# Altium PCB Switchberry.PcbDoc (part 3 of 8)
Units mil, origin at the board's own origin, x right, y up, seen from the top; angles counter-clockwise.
Board outline 4500 x 3824.8 mil, 6 copper layers (L01-TOP, L02-GND, L03-SIG, L04-SIG, L05-GND, L06-BOT), stack 49.214 mil thick; 431 components, 322 nets, 1699 pads, 1274 vias.
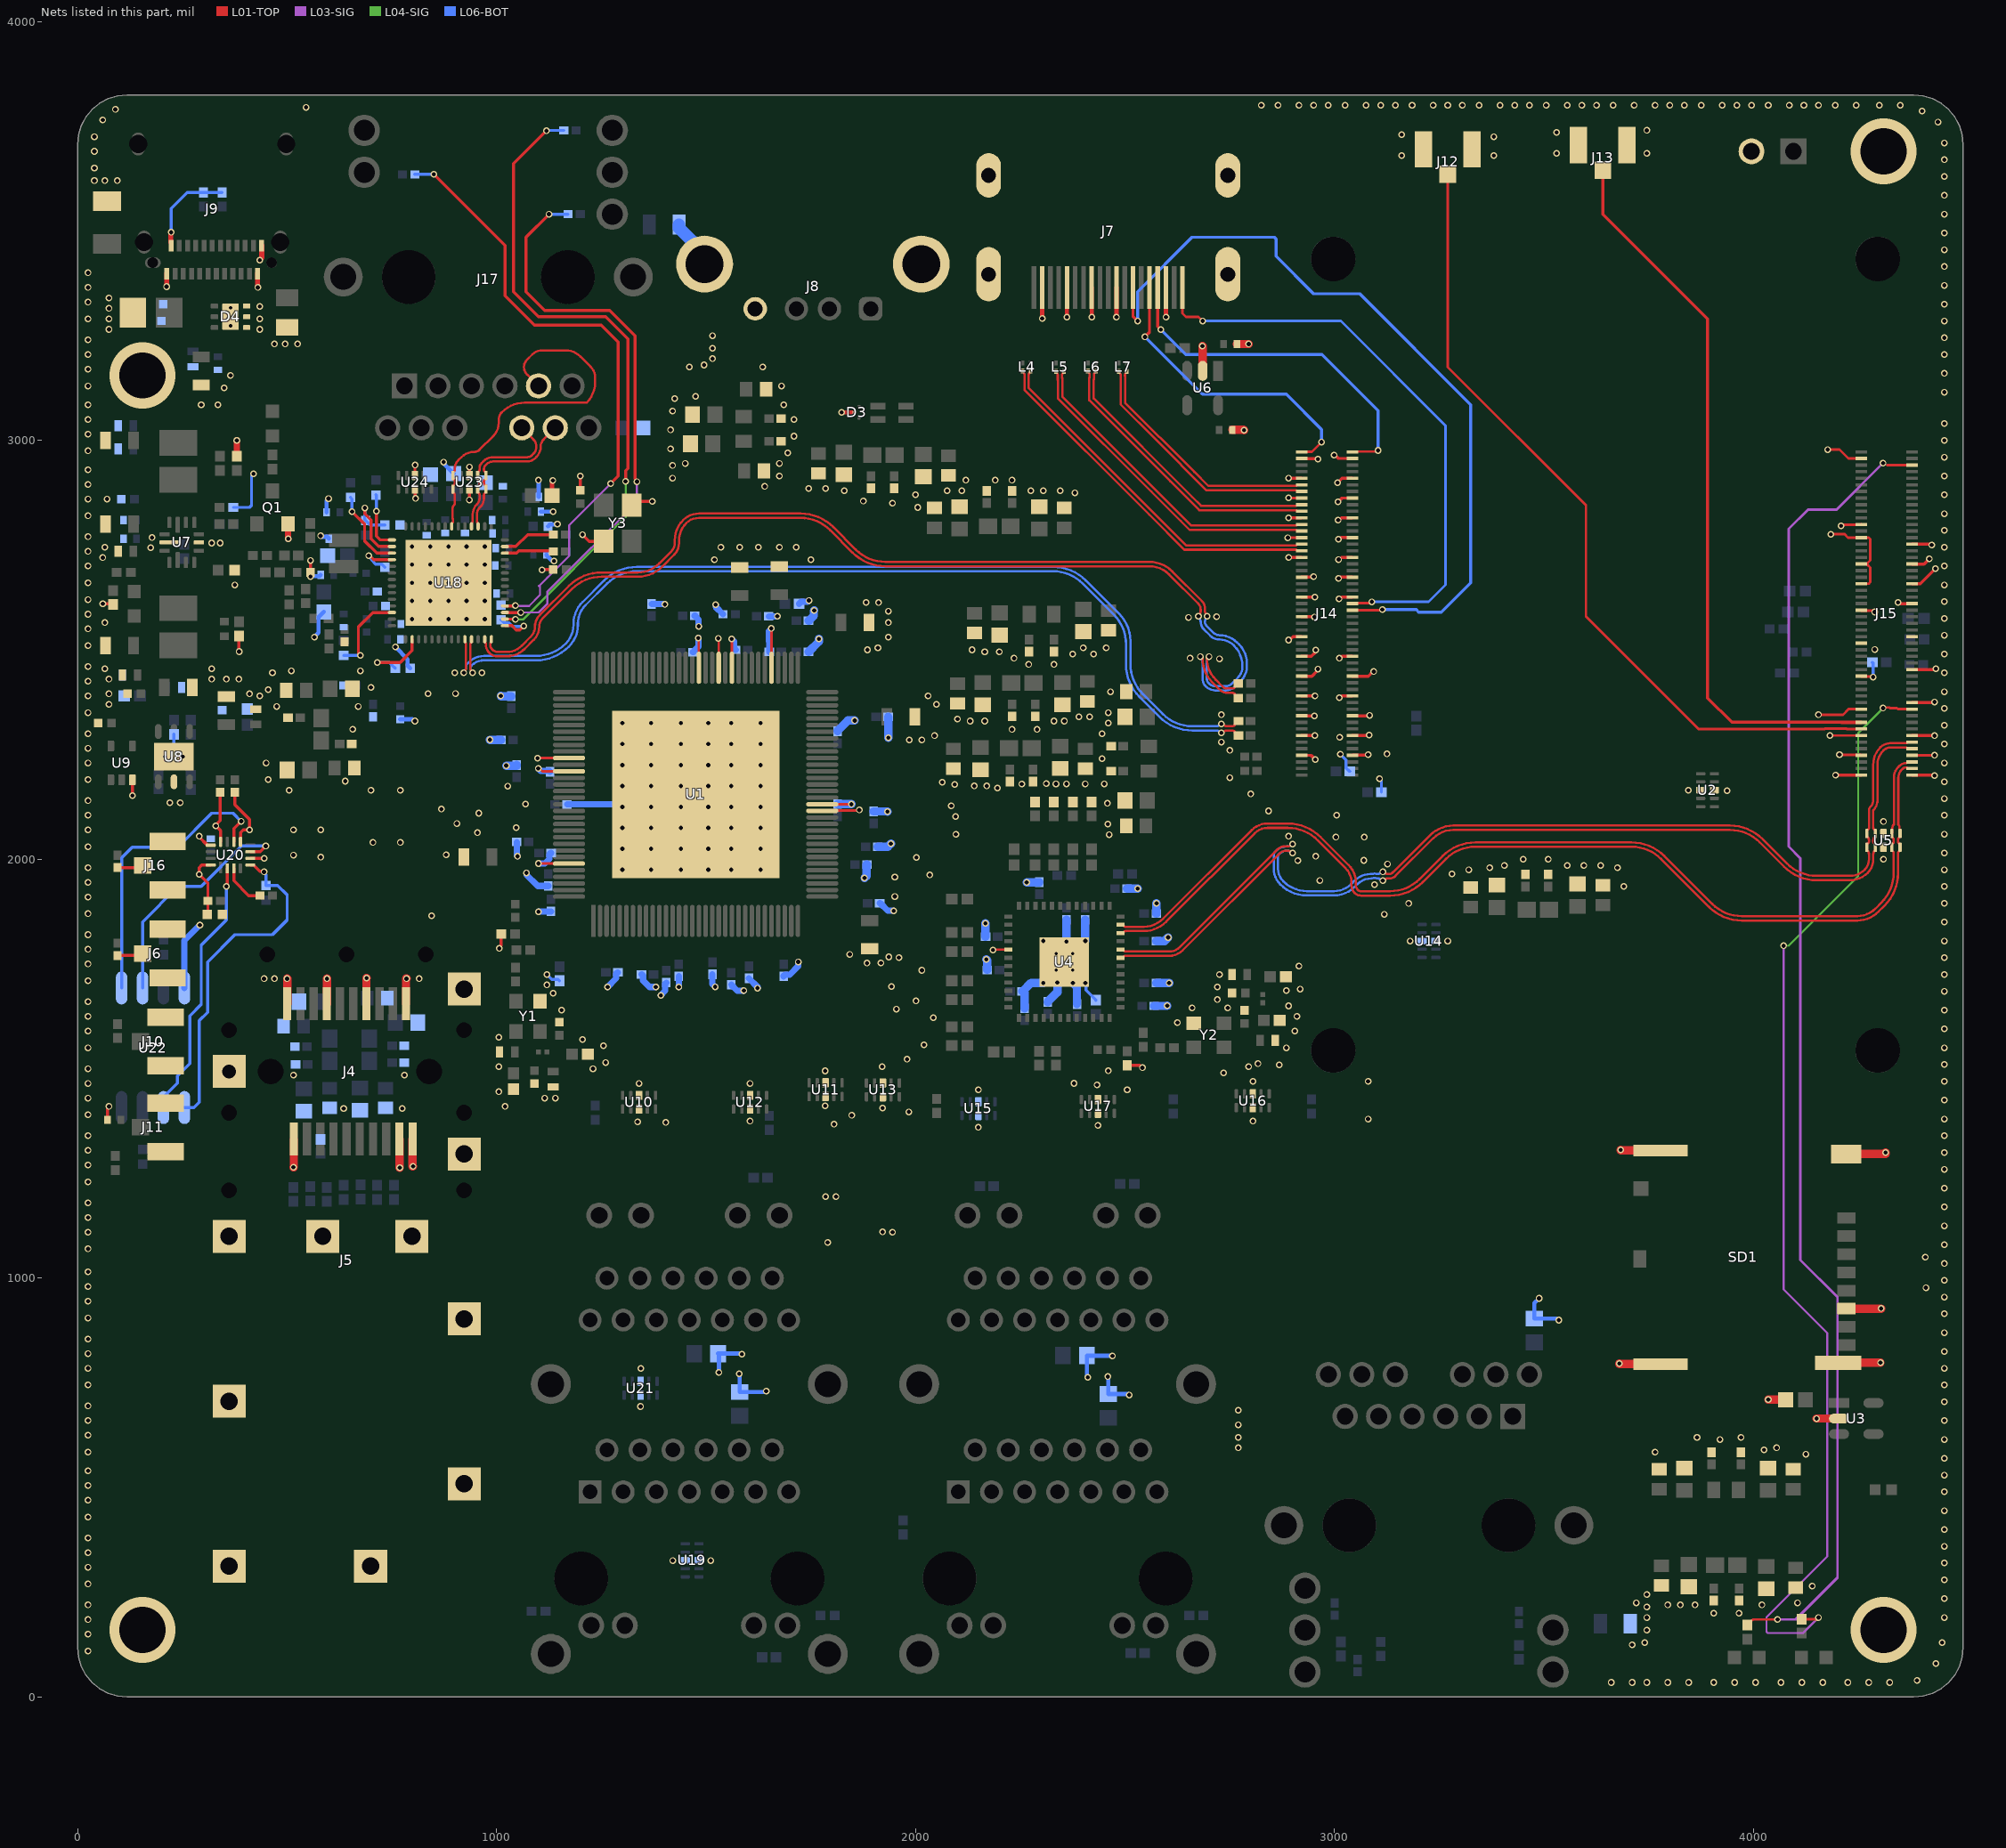
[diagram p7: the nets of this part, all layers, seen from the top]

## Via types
v1: diameter 16, hole 10, L01-TOP to L06-BOT, tented both sides, 1262 vias
v2: diameter 11.81, hole 7.87, L01-TOP to L06-BOT, tented both sides, 4 vias
v3: diameter 19.68, hole 7.87, L01-TOP to L06-BOT, tented both sides, 4 vias
v4: diameter 157.48, hole 110.24, L01-TOP to L06-BOT, tented both sides, 4 vias

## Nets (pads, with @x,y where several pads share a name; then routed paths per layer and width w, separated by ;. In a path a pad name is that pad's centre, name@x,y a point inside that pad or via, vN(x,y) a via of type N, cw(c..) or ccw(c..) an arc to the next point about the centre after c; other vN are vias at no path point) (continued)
ETH_PAIR2_N: J15.9 U4.8 U5.2 U5.9 | length 2538
  L01-TOP w5.38: U4.8@2488.86,1784.53 2490.49,1784.53 cw(c2490.49,1776.58) 2496.11,1782.2 ccw(c2501.72,1787.82) 2501.72,1779.87 2605.55,1779.87 ccw(c2605.55,1814.45) 2630,1790 2863.22,2023.22 cw(c2881.25,2005.19) 2881.25,2030.69 2888.06,2030.69 ccw(c2888.06,2039.76) 2894.47,2033.34 2895.09,2033.97 cw(c2900,2029.06) v1(2900,2036) ; v1(3115,1949) ccw(c3115,1955.94) 3119.91,1951.03 3120.53,1951.66 cw(c3126.94,1945.24) 3126.94,1954.31 3131.25,1954.31 ccw(c3131.25,1973.78) 3145.01,1960.01 3235,2050 cw(c3283.28,2001.72) 3283.28,2070 3943.56,2070 cw(c3943.56,1970) 4014.27,2040.71 4072.73,1982.26 ccw(c4150.78,2060.31) 4150.78,1949.93 4229.52,1949.93 ccw(c4229.52,2010.48) 4272.34,1967.66 ccw(c4240.17,1999.83) 4285.66,1999.83 4285.66,2012.52 cw(c4296.42,2012.52) 4288.81,2020.13 4289.07,2020.13 4289.69,2020.75 ccw(c4288.18,2022.26) 4290.31,2022.26 U5.2@4290.31,2028.56 4290.31,2033.98 ccw(c4286.05,2033.98) 4289.07,2037 4288.81,2037 4287.24,2038.57 cw(c4291.04,2042.37) 4285.66,2042.37 4285.66,2045.4 cw(c4296.42,2045.4) 4288.81,2053 4289.07,2053 4289.69,2053.63 ccw(c4288.18,2055.13) 4290.31,2055.13 U5.9@4290.31,2061.44 4290.31,2066.86 ccw(c4286.05,2066.86) 4289.07,2069.87 4288.81,2069.87 4287.24,2071.45 cw(c4291.04,2075.25) 4285.66,2075.25 4285.66,2116.42 cw(c4288.1,2116.42) 4286.38,2118.15 ccw(c4263.83,2140.69) 4295.72,2140.69 4295.72,2225.52 cw(c4344.49,2225.52) 4310,2260 cw(c4325.93,2244.07) 4325.93,2266.6 4363.47,2266.6 cw(c4363.47,2262.01) 4366.71,2265.26 ccw(c4369.95,2268.5) 4369.95,2263.91 J15.9@4377.9,2263.91
  L06-BOT w5.38: v1(2900,2036) ccw(c2900,2029.06) 2895.09,2033.97 cw(c2887.18,2041.88) 2887.18,2030.69 2885.73,2030.69 ccw(c2885.73,1994.38) 2860.05,2020.05 2859.29,2019.29 ccw(c2870.26,2008.33) 2854.75,2008.33 2854.75,1977.75 ccw(c2908.27,1977.75) 2870.43,1939.9 ccw(c2933.97,2003.45) 2933.97,1913.58 2998.42,1913.58 ccw(c2998.42,1983.07) 3047.56,1933.93 3054.2,1940.57 cw(c3087.38,1907.39) 3087.38,1954.31 3087.57,1954.37 cw(c3089.11,1949.22) 3088.34,1954.54 3093.05,1955.18 cw(c3095.11,1939.62) 3097.82,1955.08 3100.68,1954.57 ; 3100.7,1954.57 3101.27,1954.47 ccw(c3103.06,1964.69) 3103.06,1954.31 cw(c3103.06,1945.24) 3109.47,1951.66 3110.09,1951.03 ccw(c3115,1955.94) v1(3115,1949)
ETH_PAIR2_P: J15.11 U4.7 U5.1 U5.10 | length 2505.2
  L01-TOP w5.38: U4.7@2488.86,1764.84 2490.49,1764.84 ccw(c2490.49,1772.79) 2496.11,1767.17 cw(c2501.72,1761.55) 2501.72,1769.5 2605.55,1769.5 ccw(c2605.55,1814.45) 2637.34,1782.66 2869.04,2014.36 cw(c2883.4,2000) 2883.4,2020.31 2888.06,2020.31 cw(c2888.06,2011.24) 2894.47,2017.66 2895.09,2017.03 ccw(c2900,2021.94) v1(2900,2015) ; v1(3115,1970) cw(c3115,1963.06) 3119.91,1967.97 3120.53,1967.34 ccw(c3126.94,1973.76) 3126.94,1964.69 3129.1,1964.69 ccw(c3129.1,1978.97) 3139.19,1968.87 3227.66,2057.34 cw(c3283.28,2001.72) 3283.28,2080.38 3943.56,2080.38 cw(c3943.56,1970) 4021.61,2048.05 4080.07,1989.59 ccw(c4150.78,2060.31) 4150.78,1960.31 4229.52,1960.31 ccw(c4229.52,2010.48) 4265,1975 ccw(c4240.17,1999.83) 4275.28,1999.83 4275.28,2012.52 ccw(c4264.53,2012.52) 4272.13,2020.13 4271.88,2020.13 4271.25,2020.75 cw(c4272.76,2022.26) 4270.63,2022.26 U5.1@4270.63,2028.56 4270.63,2033.98 cw(c4274.89,2033.98) 4271.88,2037 4272.13,2037 4273.71,2038.57 ccw(c4269.91,2042.37) 4275.28,2042.37 4275.28,2045.4 ccw(c4264.53,2045.4) 4272.13,2053 4271.88,2053 4271.25,2053.63 cw(c4272.76,2055.13) 4270.63,2055.13 U5.10@4270.63,2061.44 4270.63,2066.86 cw(c4274.89,2066.86) 4271.88,2069.87 4272.13,2069.87 4273.71,2071.45 ccw(c4269.91,2075.25) 4275.28,2075.25 4275.28,2116.42 cw(c4288.1,2116.42) 4279.04,2125.48 ccw(c4263.83,2140.69) 4285.34,2140.69 4285.34,2225.52 cw(c4344.48,2225.52) 4302.66,2267.34 cw(c4325.93,2244.07) 4325.93,2276.98 4363.47,2276.98 ccw(c4363.47,2281.56) 4366.71,2278.32 cw(c4369.95,2275.08) 4369.95,2279.66 J15.11@4377.9,2279.66
  L06-BOT w5.38: v1(2900,2015) cw(c2900,2021.94) 2895.09,2017.03 ccw(c2887.18,2009.12) 2887.18,2020.31 2885.73,2020.31 ccw(c2885.73,1994.38) 2867.39,2012.71 2866.63,2011.95 ccw(c2870.26,2008.32) 2865.13,2008.32 2865.13,1977.75 ccw(c2908.27,1977.75) 2877.76,1947.24 ccw(c2933.97,2003.45) 2933.97,1923.95 2998.42,1923.95 ccw(c2998.42,1983.07) 3040.22,1941.27 3048.38,1949.43 cw(c3085.23,1912.58) 3085.23,1964.69 3086.66,1964.79 ccw(c3086.26,1970.16) 3086.96,1964.83 3091.61,1965.45 cw(c3095.11,1939.62) 3099.66,1965.29 3102.49,1964.79 ; 3102.5,1964.79 3103.06,1964.69 ccw(c3103.06,1973.76) 3109.47,1967.34 3110.09,1967.97 cw(c3115,1963.06) v1(3115,1970)
ETH_PAIR3_N: J15.5 U4.11 U5.4 U5.7 | length 2485.6
  L01-TOP w5.38: U4.11@2488.86,1843.58 2490.49,1843.58 cw(c2490.49,1835.64) 2496.11,1841.26 ccw(c2501.72,1846.87) 2501.72,1838.93 2544.33,1838.93 ccw(c2544.33,1904.24) 2590.51,1858.06 2802.15,2069.7 cw(c2840,2031.85) 2840,2085.38 2888.58,2085.38 cw(c2888.58,1975) 2966.63,2053.05 3033.42,1986.26 cw(c2991.94,1944.78) 3050.6,1944.78 3050.6,1937.76 ccw(c3065.63,1937.76) 3055,1927.13 ccw(c3063.12,1935.25) 3063.12,1923.77 3132.34,1923.77 ccw(c3132.34,2023.77) 3203.05,1953.05 3258.05,2008.05 cw(c3336.1,1930) 3336.1,2040.38 3708.58,2040.38 cw(c3708.58,1930) 3786.63,2008.05 3901.11,1893.57 ccw(c3971.82,1964.28) 3971.82,1864.28 4247.48,1864.28 ccw(c4247.48,1925.26) 4290.6,1882.14 4305.05,1896.59 ccw(c4234.34,1967.3) 4334.34,1967.3 4334.34,2014.75 ccw(c4328.96,2014.75) 4332.76,2018.55 4331.19,2020.13 4330.93,2020.13 cw(c4333.95,2023.14) 4329.69,2023.14 U5.4@4329.69,2028.56 4329.69,2033.98 cw(c4333.95,2033.98) 4330.93,2037 4331.19,2037 4332.76,2038.57 ccw(c4328.96,2042.37) 4334.34,2042.37 4334.34,2045.4 ccw(c4323.58,2045.4) 4331.19,2053 4330.93,2053 4330.31,2053.63 cw(c4331.82,2055.13) 4329.69,2055.13 U5.7@4329.69,2061.44 ccw(c4326.67,2064.45) 4330.93,2064.45 4330.93,2073.5 cw(c4344.31,2073.5) 4334.85,2082.96 4334.85,2194.34 cw(c4371.9,2194.34) 4345.7,2220.53 4348.84,2223.67 cw(c4363.47,2209.05) 4363.47,2229.73 ccw(c4363.47,2234.32) 4366.71,2231.07 cw(c4369.95,2227.83) 4369.95,2232.42 J15.5@4377.9,2232.42
ETH_PAIR3_P: J15.3 U4.10 U5.5 U5.6 | length 2485.3
  L01-TOP w5.38: U4.10@2488.86,1823.9 2490.49,1823.9 ccw(c2490.49,1831.84) 2496.11,1826.22 cw(c2501.72,1820.61) 2501.72,1828.55 2544.33,1828.55 ccw(c2544.33,1904.24) 2597.85,1850.72 2809.49,2062.36 cw(c2840,2031.85) 2840,2075 2888.58,2075 cw(c2888.58,1975) 2959.29,2045.71 3026.08,1978.92 cw(c2991.94,1944.78) 3040.22,1944.78 3040.22,1937.76 ccw(c3065.63,1937.76) 3047.66,1919.79 ccw(c3063.12,1935.25) 3063.12,1913.39 3132.34,1913.39 ccw(c3132.34,2023.77) 3210.39,1945.72 3265.39,2000.71 cw(c3336.1,1930) 3336.1,2030 3708.58,2030 cw(c3708.58,1930) 3779.29,2000.71 3893.77,1886.23 ccw(c3971.82,1964.28) 3971.82,1853.9 4247.48,1853.9 ccw(c4247.48,1925.25) 4297.94,1874.8 4312.39,1889.25 ccw(c4234.34,1967.3) 4344.72,1967.3 4344.72,2014.75 cw(c4350.09,2014.75) 4346.29,2018.55 4347.87,2020.13 4348.12,2020.13 ccw(c4345.11,2023.14) 4349.37,2023.14 U5.5@4349.37,2028.56 4349.37,2033.98 ccw(c4345.11,2033.98) 4348.12,2037 4347.87,2037 4346.29,2038.57 cw(c4350.09,2042.37) 4344.72,2042.37 4344.72,2045.4 cw(c4355.47,2045.4) 4347.87,2053 4348.12,2053 4348.75,2053.63 ccw(c4347.24,2055.13) 4349.37,2055.13 U5.6@4349.37,2061.44 cw(c4352.38,2064.45) 4348.12,2064.45 4348.12,2075.97 ccw(c4338.24,2075.97) 4345.23,2082.96 4345.23,2194.34 cw(c4371.9,2194.34) 4353.04,2213.19 4356.18,2216.34 cw(c4363.47,2209.05) 4363.47,2219.35 cw(c4363.47,2214.77) 4366.71,2218.01 ccw(c4369.95,2221.25) 4369.95,2216.67 J15.3@4377.9,2216.67
ETH_SYNC_IN: J12.1 J15.16 | length 1960.3
  L01-TOP w6: J12.1@3270,3634.96 3270,3175 3600,2845 3600,2580 3868.84,2311.16 4169.47,2311.16 4170.31,2312 4221.84,2312 4222.68,2311.16 J15.16@4256.64,2311.16
ETH_SYNC_OUT: J13.1 J15.18 | length 1754.3
  L01-TOP w7.27: J13.1@3640,3645 3640,3540 3890,3290 3890,2385 3948.09,2326.91 4209.76,2326.91
  L01-TOP w8: 4209.76,2326.91 J15.18@4256.64,2326.91 J15.18@4256.57,2326.84
FLASH_CS: U20.10 U22.1 | length 705.1
  L01-TOP w7.27: U20.10@372.87,2041.5 372.87,2073.26 v1(390.43,2090.82)
  L06-BOT w7.27: U22.1@105,1692.72 105,2003.83 130.35,2029.19 238.84,2029.19 319.66,2110 371.26,2110 v1(390.43,2090.82)
FLASH_DIN: R139.1 U20.5 U22.5 | length 808.2
  L01-TOP w7.27: U20.5@412.24,1986.38 420.12,1986.38 434.83,1971.67 443.33,1971.67 v1(445,1970)
  L06-BOT w7.27: U22.5@255,1407.28 277.28,1407.28 290,1420 290,1615 310,1635 310,1755 375,1820 465,1820 500,1855 500,1915 477.2,1937.8 R139.1@450,1937.8 450,1962.64 445,1967.64 v1(445,1970)
FLASH_DOUT: U20.7 U22.2 | length 569.3
  L01-TOP w7.27: U20.7@412.24,2017.87 435.41,2017.87 v1(449.07,2031.54)
  L06-BOT w7.27: U22.2@155,1692.72 155,1850.39 239.61,1935 295,1935 391.54,2031.54 v1(449.07,2031.54)
FLASH_SCK: U20.2 U22.6 | length 634.2
  L01-TOP w7.27: v1(355,1935) 355,1937.36 357.13,1939.49 U20.2@357.13,1978.5
  L06-BOT w7.27: U22.6@205,1407.28 205,1432.87 237.99,1465.87 237.99,1482.32 268.07,1512.4 268.07,1626.44 295,1653.37 295,1795 355,1855 v1(355,1935)
GND: C1.2 C2.1 C3.2 C4.2 C5.1 C6.2 C7.2 C8.1 C9.2 C10.2 C11.1 C12.2 C13.2 C14.2 C15.2 C16.2 C17.2 C18.2 C19.2 C20.2 C21.2 C22.2 C23.2 C24.2 C25.2 C26.1 C27.1 C28.1 C29.1 C30.2 C31.1 C33.1 C34.1 C35.2 C36.2 C37.2 C38.2 C39.2 C40.1 C41.1 C42.2 C43.2 C44.2 C45.2 C46.2 C47.2 C48.2 C49.2 C50.1 C51.1 C52.2 C53.2 C54.2 C55.1 C56.2 C57.2 C58.2 C59.1 C60.2 C61.2 C62.2 C63.2 C64.1 C65.2 C66.2 C67.1 C68.2 C69.2 C70.2 C71.1 C72.2 C73.2 C74.1 C75.2 C76.2 C77.2 C78.2 C79.1 C80.2 C81.2 C82.1 C83.2 C84.2 C85.2 C86.2 C87.2 C88.2 C89.2 C90.2 C91.1 C92.2 C93.2 C94.1 C95.2 C96.2 C97.2 C98.2 C99.1 C100.2 C101.2 C102.1 C103.2 C104.2 C105.2 C106.2 C107.1 C108.2 C109.2 C110.1 C111.2 C112.2 C113.2 C114.2 C115.2 C116.2 C117.2 C118.2 C119.2 C120.1 C121.2 C122.2 C123.1 C124.2 C125.2 C126.2 C127.2 C128.2 C129.2 C130.2 C131.2 C132.2 C133.2 C134.2 C135.1 C136.2 C137.2 C138.1 C139.2 C140.2 C141.2 C142.2 C143.2 C144.2 C145.2 C146.2 C147.2 C148.2 C149.2 C150.1 C151.2 C152.2 C153.1 C154.2 C155.2 C156.2 C157.2 C158.1 C159.2 C160.2 C161.1 C162.2 C163.2 C164.2 C165.2 C166.1 C167.2 C168.2 C169.1 C170.2 C171.2 C172.2 C173.2 C176.1 C177.1 C178.1 C179.1 C180.1 C181.1 C182.2 C186.1 C187.1 C188.1 C189.1 C190.1 C191.1 C192.1 C193.1 C194.1 C195.1 C196.1 C197.1 C198.1 C199.1 C200.1 C201.1 C202.1 C203.1 C204.1 C205.1 C206.1 C207.2 C208.1 C209.2 C210.2 C211.2 C212.2 C213.2 D3.1 D4.1 D4.2 D4.3 D4.7 FB3.1 FB4.1 J4.1 J4.9 J4.10 J4.11 J4.14 J4.17 J4.20 J5.MH1 J5.MH2 J5.MH3 J5.MH4 J5.MH5 J5.MH6 J5.MH7 J5.MH8 J5.MH9 J5.MH10 J5.MH11 J5.MH12 J5.MH13 J5.MH14 J5.MH15 J5.MH16 J5.MH17 J5.MH18 J5.MH19 J5.MH20 J6.2 J6.3 J7.2 J7.5 J7.8 J7.11 J7.17 J7.Shell J8.4 J8.Shell J9.A1 J9.A12 J9.B1 J9.B12 J10.2 J10.3 J11.2 J11.3 J12.2 J12.3 J13.2 J13.3 J14.7 J14.8 J14.13 J14.14 J14.19 J14.20 J14.25 J14.26 J14.31 J14.32 J14.37 J14.38 J14.44 J14.50 J14.55 J14.56 J14.61 J14.62 J14.67 J14.68 J14.73 J14.74 J14.79 J14.80 J14.85 J14.86 J14.91 J14.92 J14.97 J14.98 J15.1 J15.2 J15.7 J15.8 J15.13 J15.14 J15.22 J15.23 J15.32 J15.33 J15.42 J15.43 J15.52 J15.53 J15.59 J15.60 J15.65 J15.66 J15.71 J15.74 J15.98 J16.2 J16.3 J18.2 Q1.2 R8.2 R9.1 R10.1 R11.1 R12.1 R13.1 R42.1 R50.2 R51.2 R52.2 R59.1 R60.1 R65.2 R66.2 R67.1 R68.1 R73.1 R76.2 R77.1 R89.1 R105.1 R107.1 R111.2 R122.2 R130.1 R134.1 R135.1 R147.1 R148.1 R149.1 SD1.6 SD1.11 SD1.12 SD1.13 SD1.14 U1.46 U1.47 U1.69 U1.75 U1.77 U1.80 U1.107 U1.109 U1.123 U1.129 U2.3 U2.8 U3.2 U4.29 U4.49 U5.3 U5.8 U6.2 U7.2 U7.9 U8.2 U8.7 U9.3 U10.3 U10.8 U11.3 U11.8 U12.3 U12.8 U13.3 U13.8 U14.3 U14.8 U15.3 U15.8 U16.3 U16.8 U17.3 U17.8 U18.PAD U19.3 U19.8 U20.6 U20.13 U21.3 U21.8 U22.4 U23.3@935,2883.56 U23.8@935,2916.44 U24.3@805,2883.56 U24.8@805,2916.44 Y1.2 Y2.2 Y3.2 Y3.4 | length 9045.6
  L01-TOP w6: v1(1097.56,2241.5) 1097.62,2241.56 1172.76,2241.56 U1.107@1172.82,2241.61 ; v1(1099.38,2216.55) 1102.09,2216.55 1108.55,2210.09 U1.109@1172.79,2210.09 ; v1(1100,1990) 1100.18,1989.82 1172.64,1989.82 U1.123@1172.82,1989.65 ; v1(1481.58,2528.36) 1482.23,2527.71 1482.23,2457.83 U1.80@1482.87,2457.18 ; v1(1529.21,2527.44) 1530.12,2526.53 U1.77@1530.12,2457.18 ; v1(1561.12,2525.93) 1561.37,2525.68 1561.37,2457.43 U1.75@1561.61,2457.18 ; v1(1655.72,2551.1) 1656.3,2550.53 1656.3,2519.58 1656.1,2519.39 U1.69@1656.1,2457.18 ; U1.46@1777.18,2115.63 1778.09,2116.53 1864.41,2116.53 v1(1865.44,2117.56) ; U1.47@1777.18,2131.38 v1@1846.6,2131.41 ; v1(2184.37,1783.66) 2185.23,1784.53 U4.29@2221.14,1784.53 ; v1(4155,2345) 4213.45,2345 4226.86,2358.4 J15.22@4256.64,2358.4 ; v1(4177,2978) 4205.28,2978 4226.46,2956.83 J15.98@4256.64,2956.83 ; v1@4182.08,2295.41 4222.87,2295.41 J15.14@4256.64,2295.41 J15.14@4266.48,2295.41 ; v1(4184,2776) 4217.28,2776 4225.43,2767.85 J15.74@4256.64,2767.85 4256.82,2767.67 4274.9,2767.67 4278.42,2764.16 4278.42,2713.36 4270.9,2705.84 ; v1(4205,2249.96) 4205.9,2249.06 4255.74,2249.06 J15.8@4256.64,2248.17 ; J15.32@4256.64,2437.14 4257.57,2436.2 4283.8,2436.2 v1(4285,2435) ; J15.52@4256.64,2594.62 4257.57,2593.69 4285.64,2593.69 v1(4289,2590.33) ; J15.60@4256.64,2657.61 4256.82,2657.79 4274.9,2657.79 4278.42,2661.31 4278.42,2696.36 4270.2,2704.58 4256.91,2704.58 J15.66@4256.64,2704.86
  L01-TOP w7.27: v1(60.17,2609.83) 83.44,2609.83 R77.1@85,2608.27 ; C188.1@71.68,1378.14 71.68,1404.31 75,1407.64 v1(75,1410) ; U9.3@130.59,2189.65 130.59,2152.17 v1(131,2151.76) ; v1(290,2055) 290,2053.5 309.88,2033.62 U20.13@317.76,2033.62 ; R60.1@385,2533.27 385,2496.16 v1(385.42,2495.75) ; U20.6@412.24,2002.13 v1(445.05,2002.12) ; C62.2@555.75,2685 v1(555.75,2713.37) ; U24.3@805,2883.56 805.7,2882.86 805.7,2862.06 v1(806.4,2861.36) ; U24.8@805,2916.44 805,2940.84 v1(805.23,2941.07) ; v1(934.69,2857.87) 935,2858.18 U23.3@935,2883.56 ; U23.8@935,2916.44 935,2931.5 v1(935,2936.63) ; v1(1006.37,1787.28) 1006.37,1789.64 1010.88,1794.15 R105.1@1010.88,1821.69 ; v1(1108.22,2690.96) 1109.21,2691.95 C186.1@1134.82,2691.95 ; C187.1@1200,2880.75 v1(1200,2915) ; v1(1205,2775) 1220.88,2759.12 Y3.2@1255.67,2759.12 ; Y3.4@1322.6,2845.73 1331.33,2854.46 v1(1371.38,2854.46) ; R107.1@2505,1508.27 2535.58,1508.27 v1(2541.33,1502.52) ; v1(2888.49,2767.69) 2921.04,2767.69 J14.74@2921.2,2767.85 ; v1(2890,2523.37) 2892.36,2523.37 2900.33,2531.33 2920.9,2531.33 J14.44@2921.2,2531.63 ; v1(2890,2815) 2890.05,2815.05 J14.80@2921.2,2815.09 J14.80@2921.2,2815.09 ; v1(2890.02,2862.62) 2890.3,2862.34 J14.86@2921.2,2862.34 ; v1(2890,2910) 2890.21,2909.79 2921,2909.79 J14.92@2921.2,2909.58 ; v1(2890.53,2720.31) 2890.83,2720.61 J14.68@2921.2,2720.61 ; J14.8@2921.2,2248.17 2943.83,2248.17 v1(2954,2238) ; J14.14@2921.2,2295.41 2921.35,2295.26 v1(2952.69,2295.26) ; J14.20@2921.2,2342.65 2951.49,2342.65 v1(2952.01,2342.13) ; J14.26@2921.2,2389.9 2952.9,2389.9 v1(2953.2,2390.19) ; J14.32@2921.2,2437.14 2945.89,2437.14 2958.33,2449.58 2958.33,2452.6 v1(2960,2454.27) ; J14.38@2921.2,2484.39 2944.39,2484.39 2953.33,2493.33 2953.33,2497.6 v1(2955,2499.27) ; J14.50@2921.2,2578.87 2951.31,2578.87 v1(2951.67,2578.52) ; J14.56@2921.2,2626.12 2952.98,2626.12 v1(2953.03,2626.07) ; J14.62@2921.2,2673.36 2921.51,2673.66 2948.66,2673.66 v1(2950,2675) ; J14.98@2921.2,2956.83 2921.51,2956.52 2958.48,2956.52 v1(2960,2955) ; v1(2999,2965) 3001.36,2965 3009.54,2956.83 J14.97@3042.46,2956.83 ; v1(3007,2899) 3007.2,2899 3017.78,2909.58 J14.91@3042.46,2909.58 ; v1(3007.87,2853.02) 3008.46,2853.02 3017.78,2862.34 J14.85@3042.46,2862.34 ; v1(3008.46,2809.5) 3010.82,2809.5 3016.42,2815.09 J14.79@3042.46,2815.09 ; v1(3009,2764) 3011.36,2764 3015.21,2767.85 J14.73@3042.46,2767.85 ; v1(3009.51,2670.49) 3011.87,2670.49 3014.74,2673.36 J14.61@3042.46,2673.36 ; v1(3009.51,2715.49) 3011.87,2715.49 3016.98,2720.61 J14.67@3042.46,2720.61 ; v1(3010.61,2621.66) 3012.97,2621.66 3017.43,2626.12 J14.55@3042.46,2626.12 ; v1(3011,2386) 3013.36,2386 3017.26,2389.9 J14.25@3042.46,2389.9 ; v1(3011,2480) 3013.36,2480 3017.75,2484.39 J14.37@3042.46,2484.39 ; J14.7@3042.46,2248.17 3042.77,2248.47 3078.47,2248.47 v1(3080,2250) ; J14.13@3042.46,2295.41 3042.77,2295.71 3082.04,2295.71 v1(3082.6,2296.27) ; J14.19@3042.46,2342.65 3082.28,2342.65 v1(3083.28,2343.65) ; J14.31@3042.46,2437.14 3080.27,2437.14 3091.21,2448.08 v1(3093.57,2448.08) ; v1(4195.52,2201.18) 4195.78,2200.92 J15.2@4256.64,2200.92 ; v1(4345,2613) 4347.36,2613 4349.99,2610.37 J15.53@4377.9,2610.37 ; J15.1@4377.9,2200.92 4430.86,2200.92 v1(4431.72,2200.06) ; J15.7@4377.93,2248.2 v1@4431.69,2248.2 ; J15.13@4377.9,2295.41 4378.1,2295.2 4431.52,2295.2 v1(4431.72,2295) ; J15.23@4377.9,2374.15 4378.2,2374.45 4430.69,2374.45 v1(4431.72,2375.48) ; J15.33@4377.9,2452.89 4430.53,2452.89 4432.64,2455 v1(4435,2455) ; J15.59@4377.9,2657.61 4378.2,2657.92 4397.92,2657.92 v1(4433.84,2693.84) ; J15.65@4377.9,2704.86 4406.92,2704.86 v1(4419.58,2717.52) ; J15.71@4377.9,2752.1 4420.54,2752.1 4422.64,2750 v1(4425,2750)
  L01-TOP w10: C207.2@1132.27,2868.31 1132.27,2902.41 v1(1134.27,2904.42) ; v1(1823.38,3066.63) 1823.69,3066.95 D3.1@1853.13,3066.95 ; v1(2302.14,3291.19) J7.2@2302.2,3365 ; J7.5@2361.26,3365 2361.26,3293.98 v1(2361.34,3293.98) ; J7.8@2420.31,3365 v1(2420.4,3293.98) v1(2420.4,3293.98) ; J7.11@2479.37,3365 2479.37,3293.98 v1(2479.45,3293.98) ; J7.17@2597.48,3365 2597.48,3293.98 v1(2597.56,3293.98)
  L01-TOP w12: v1(212.29,3367.01) 212.99,3367.7 J9.A12@212.99,3398.07 ; J9.B1@222.74,3472.78 222.74,3476.43 222.41,3476.75 222.41,3494.53 223.48,3495.6 v1(223.48,3496.68) ; J9.A1@429.53,3398.07 429.53,3365.47 v1(430,3365) ; v1(435,3430) 435,3431.62 439.37,3435.99 J9.B12@439.37,3465
  L01-TOP w15: R59.1@380,2961.73 v1(380,3000) ; Q1.2@502.4,2800.63 502.4,2765.3 v1(502.78,2764.92)
  L01-TOP w20: v1(500,1715) 500.24,1714.76 J4.20@500.24,1654.89 ; v1(515,1265) 515.99,1265 J4.1@515.99,1332.05 ; J4.17@594.73,1654.89 594.73,1714.73 v1(595,1715) ; J4.14@689.22,1654.89 689.22,1716.55 v1(689.7,1716.55) ; J4.9@767.96,1332.05 767.96,1263.99 v1(768.89,1263.99) ; J4.11@783.71,1654.89 783.71,1715 v1(785,1715) ; J4.10@799.46,1332.05 799.46,1266.91 v1(800.65,1266.91) ; v1(2684.52,3225.07) 2685,3224.59 U6.2@2685,3166.07 ; C34.1@2755.75,3025 2782.81,3025 v1(2783.63,3024.18) ; C33.1@2766.5,3230 v1(2795,3230) ; v1(3679.43,796.12) 3679.43,794.88 SD1.12@3777.76,794.88 ; v1(3682.88,1306.08) 3682.88,1305.12 SD1.13@3777.76,1305.12 ; v1(4035,710) C15.2@4076.36,710 ; v1(4150,665) U3.2@4203.93,665 ; SD1.11@4202.17,798.03 4302.78,798.03 v1(4302.78,798.27) ; SD1.14@4221.26,1296.46 4315,1296.46 v1(4315,1300) ; SD1.6@4221.85,927.17 4304.51,927.17 v1(4304.51,927.59)
  L06-BOT w7.27: v3(208.35,2245) 230,2266.65 R73.1@230,2298.27 ; v1(223.48,3496.68) 223.48,3553.48 261.73,3591.73 R66.2@300,3591.73 R65.2@345,3591.73 ; R67.1@371.73,2840 410,2840 415,2845 415,2915 v1(420,2920) ; v1(1120,1725) 1131.54,1713.46 1146.54,1713.46 R51.2@1150,1710 ; v1(2405,1705) 2406.67,1703.33 2406.67,1687.78 2430,1664.45 R89.1@2430,1663.46 ; v1(3013.75,2250.88) 3027.57,2237.05 3027.57,2218.18 3035.75,2210 R52.2@3036.73,2210 ; v1(3107.4,2192.35) 3107.4,2189.99 3111.73,2185.65 R9.1@3111.73,2160 ; R111.2@4283.27,2470 4285,2468.27 v1(4285,2435)
  L06-BOT w10: v1(555.75,2674.76) 556.9,2675.91 577.01,2675.91 C196.1@579.88,2678.82 ; v1(565,2530) 565,2531.62 574.68,2541.31 574.68,2577.75 C212.2@587.5,2590.56 ; v1(579.81,2772.14) 581.43,2772.14 583.73,2769.84 596.38,2769.84 599.25,2766.97 C197.1@599.25,2765 ; C199.1@594.07,2828.31 594.07,2856.25 v1(598.88,2861.06) ; v1(758.34,2506.66) 787.66,2477.34 787.66,2462.23 R148.1@793.85,2456.04 ; R135.1@770,2334.17 799.21,2334.17 803.38,2330 v1(805,2330) ; v1(873.47,2948.32) 874.62,2947.17 874.62,2943.47 C211.2@897.61,2920.48 ; v1(1100,2905) 1100.37,2904.63 1100.37,2865.37 C205.1@1100.75,2865 ; C194.1@1105.75,2830 v1(1135,2830) ; C193.1@1119.06,2727.56 1119.06,2725.59 1131.34,2713.31 1135.68,2713.31 v1(1136.83,2712.16) ; R134.1@1122.72,2795 1126.57,2798.85 1143.85,2798.85 v1(1145,2800) ; v1(1530.58,775.18) 1530.58,817.96 C31.1@1528.54,820 1583.58,820 v1(1585.2,818.38) ; v1(1579.08,771.91) 1580,771 C26.1@1580,728.54 1641.69,728.54 v1(1643.48,730.34) ; v1(2410.96,763.5) 2408.54,765.91 C29.1@2408.54,815 2469.38,815 v1(2469.77,814.61) ; v1(2458.77,765.14) 2460,763.92 C27.1@2460,723.54 2507.52,723.54 v1(2509.89,721.18) ; v1(3487.94,951.95) 3476.88,940.89 C28.1@3476.88,903.89 3530.86,903.89 v1(3534.84,899.9)
  L06-BOT w15: U22.4@255,1692.72 255,1806.34 v1(291.8,1843.13) ; C132.2@1047.86,2041.34 1047.86,2009.3 v1(1050,2007.15) ; v1(1071.37,1967.56) 1071.56,1967.37 1071.56,1962.5 1084.41,1949.65 1084.87,1949.65 1098.16,1936.36 C131.2@1123.5,1936.36 ; v1(1099.38,2216.55) 1099.66,2216.55 1105.21,2211 1125.29,2211 C118.2@1127.53,2208.76 ; v1(1100,1875) 1100.61,1875.61 C116.2@1130,1875.61 ; v1(1100,1990) 1100.19,1990.19 1115.61,1990.19 1126.06,2000.65 1126.06,2012.42 1128.64,2015 C117.2@1130,2015 ; C133.2@1168.09,2131.1 1293.63,2131.1 1299.73,2125 v1(1300,2125) ; v1(1265,1695) 1265,1695.19 1285.45,1715.65 1285.45,1727.42 1288.03,1730 C130.2@1289.39,1730 ; C115.2@1345.61,1725 1346.97,1725 1349.55,1722.42 1349.55,1710.65 1365,1695.19 1379.81,1695.19 v1(1380,1695) ; C142.2@1370,2609.39 1400.1,2609.39 1401.03,2608.47 v1(1401.3,2608.47) ; v1(1392,1675.19) 1392,1675.46 1402.42,1685.88 1402.42,1703.03 C147.2@1405,1705.61 ; v1(1435,1695) C129.2@1435,1720.61 ; C163.2@1468.45,2494.44 1469.81,2494.44 1472.39,2497.02 1472.39,2498.38 1481.39,2507.38 1481.39,2528.17 v1(1481.58,2528.36) ; C156.2@1472.78,2581.29 1474.14,2581.29 1476.72,2578.71 1476.72,2577.35 1482.1,2571.97 1482.1,2556.46 v1(1482.29,2556.27) ; C128.2@1515,1725.61 1515,1702.43 v1(1521.88,1695.55) ; v1(1522.79,2607.56) 1522.79,2602.45 R42.1@1540.24,2585 ; C114.2@1560,1700.61 1574.19,1686.42 v1(1590.01,1686.42) ; v1(1561.12,2525.93) 1561.12,2525.66 1566.67,2520.11 1566.67,2502.58 1569.25,2500 C155.2@1570.61,2500 ; C146.2@1602.01,1715.88 1622.67,1695.22 v1(1622.67,1692.39) ; C164.2@1649.39,2580 v1(1670,2580) ; C173.2@1650.61,2495 1650.61,2519.87 1649.8,2520.68 1649.8,2544.9 1655.72,2550.83 v1(1655.72,2551.1) ; C127.2@1685,1720.61 1685,1721.97 1687.58,1724.55 1699.35,1724.55 1719.81,1745 1719.81,1754.81 v1(1720,1755) ; R50.2@1721.73,2610 1726.04,2614.31 1741.66,2614.31 1745.11,2617.76 v1(1745.38,2617.76) ; C113.2@1914.39,1895 1915.75,1895 1933.54,1877.21 1947.26,1877.21 v1(1947.45,1877.02)
  L06-BOT w20: v1(983.89,2285.37) 984.26,2285 C141.2@1010.61,2285 ; v1(1010,2390) 1010.61,2389.39 C172.2@1035,2389.39 ; v1(1023.02,2223.58) 1047.43,2223.58 1047.51,2223.66 C148.2@1047.51,2224.97 ; C143.2@1744.39,2495 1769.08,2519.69 v1(1769.08,2526.27) ; C140.2@1744.39,2570 1745.75,2570 1757,2581.25 1757,2593.09 v1(1757.98,2594.06) ; C145.2@1813.74,2131.68 1846.39,2131.68 v1(1846.63,2131.44) ; C144.2@1814.1,2305.69 1814.1,2307.04 1838.29,2331.23 v1(1854.56,2331.23) ; v1(1878.08,1955.41) 1882.73,1960.06 1882.73,1986.88 1882.81,1986.96 C126.2@1884.17,1986.96 ; C112.2@1900,2114.39 1931.73,2114.39 v1(1932.62,2113.5) ; C125.2@1909.39,2030 1909.47,2030.08 1933.67,2030.08 v1(1940.92,2037.33) ; C171.2@1934.39,2340 1935,2339.39 v1(1935,2290) ; v1(2166.46,1846.83) 2166.87,1846.42 C85.2@2166.87,1814.88 ; v1(2168.52,1761.32) 2171.04,1758.8 C84.2@2171.04,1736.04 ; C77.2@2254.39,1685 C77.2@2255.75,1685 ; C89.2@2260,1644.39 2260,1680.75 C77.2@2255.75,1685 ; v1(2265,1945) 2295.29,1945 C86.2@2295.64,1945.35 ; v1(2305,1705) 2275.75,1705 C77.2@2255.75,1685 ; C182.2@2315,1659.39 2338.4,1682.79 v1(2338.4,1705.69) ; C87.2@2360,1855.61 2360,1803.85 v1(2360.24,1803.61) ; v1(2375.41,1705) 2385,1695.41 C69.2@2385,1654.39 ; v1(2405,1805) C76.2@2405,1855.61 ; C88.2@2504.39,1930 v1(2530,1930) ; C104.2@2569.39,1650 2600.15,1650 v1(2600.44,1650.29) ; C97.2@2574.39,1705 v1(2605,1705) ; C96.2@2574.39,1805 2594.25,1805 v1(2602.74,1813.5) ; C105.2@2574.39,1870 2574.39,1894.39 v1(2575,1895)
  L06-BOT w30: FB4.1@1435.43,3515 1435.43,3507.13 1496.34,3446.22 J8.Shell@1496.34,3420.87
  other v1: 3660,35 3710,35 3745,35 3795,35 3845,35 3905,35 3955,35 4005,35 4065,35 4115,35 4165,35 4225,35 4275,35 4325,35 4390,40 4435,80 25,110 3710,125 3740,130 4450,130 25,150 3745,160 25,185 3745,190 4455,190 3905,200 3965,200 3745,215 25,220 3795,220 3825,220 3860,220 4020,220 3720,225 4105,225 4455,235 3745,245 4140,265 25,270 4455,280 25,310 4455,320 1420.39,326.06 1511.23,326.06 25,345 4455,360 25,380 4455,400 25,430 4455,445 25,470 4455,490 25,505 4455,530 25,540 4455,570 4125,580 25,585 3765,585 4025,590 2770,595 4055,595 3920,615 4455,615 2770,620 3865,620 3970,620 25,625 2770,650 25,660 4455,660 2770,685 1343.61,693.73 25,695 4455,705 25,745 4455,745 25,785 1344.04,784.48 4455,785 25,820 4455,825 25,855 4455,870 25,905 4455,915 25,945 4455,955 4411.31,977.26 25,980 4455,995 25,1015 4455,1035 4410,1050 25,1070 4455,1080 1790,1085 25,1110 1945,1110 1921.06,1110.35 4455,1125 25,1145 4455,1170 25,1180 1785,1195 1810,1195 4455,1215 25,1230 4455,1260 25,1270 4455,1300 25,1305 25,1340 4455,1340 2149.55,1360.03 2435,1365 1805.39,1367.55 1403.8,1371.83 1336.38,1373.44 1605,1375 2805,1375 3080,1380 4455,1380 1847.46,1388.72 25,1390 1984.15,1396.92 635,1405 775,1405 1921.23,1406.23 1020,1410 1784.22,1411.6 4455,1425 25,1430 1115,1430 1140,1430 1005,1445 2150,1450 2505,1450 2432.88,1461.46 25,1465 1340,1465 1605,1465 2377.88,1465.13 2805,1470 3080,1470 4455,1470 515,1485 780,1485 2735,1490 1784.22,1494.9 2460,1495 25,1500 1230,1500 1005,1505 1920,1505 2795,1505 2867.98,1509.14 4455,1510 2817.32,1511.98 1260,1515 1979.35,1522.68 25,1550 2885,1550 4455,1550 1255,1555 2020.18,1557.03 1205,1570 1005,1575 25,1590 2905,1590 4455,1595 2625,1610 2042.49,1621.77 25,1625 2910,1625 1155,1640 4455,1640 1954,1642.44 2660,1645 2745,1645 2890,1650 25,1660 2000.8,1661.91 2720,1665 1135,1680 4455,1685 2885.15,1686.51 2917.81,1690.18 2720,1695 1942.61,1696.39 1120,1700 25,1710 445,1715 470,1715 815,1715 2725,1725 4455,1725 2015,1735 2915,1745 25,1750 1884.28,1752.14 1917.34,1752.44 1960,1765 4455,1765 1935.94,1766.9 1842.95,1773.1 25,1785 2305,1805 3180,1805 3270,1805 4455,1805 25,1820 4455,1850 845,1865 3118.88,1868.85 25,1870 3176.59,1894.57 4455,1895 25,1910 1950.37,1911.29 3690,1935 4455,1935 3095.11,1939.62 25,1945 2964.88,1949.5 1950.37,1957.61 2033.97,1962.56 3280,1965 1300,1975 1368.45,1975 1440,1975 1505,1975 1560,1975 1630,1975 3320,1975 4455,1975 25,1980 3370,1980 3675,1980 3405,1985 3555,1985 3595,1985 3635,1985 3126.43,1988.84 2912.04,1997.12 3069.64,1997.45 3450,2000 3510,2000 4310,2000 580,2005 2001.93,2004.51 2955.14,2007.21 515,2010 879.56,2010.64 4455,2015 1300,2025 1368.45,2025 1440,2025 1505,2025 1560,2025 1630,2025 25,2030 705,2040 770,2040 3003.22,2052.86 3070.67,2052.86 2890,2055 2462.23,2058.97 2096.02,2059.86 4455,2060 954.33,2063.46 25,2070 515,2070 580,2070 1300,2075 1368.45,2075 1440,2075 1505,2075 1560,2075 1630,2075 1047.02,2075.78 2458.93,2083.99 905.02,2085.5 4310,2090 2095.15,2102.39 25,2105 3005,2105 4455,2105 957.29,2110.05 2842.53,2115.4 868.43,2119.82 1368.45,2125 1440,2125 1505,2125 1560,2125 1630,2125 2085.24,2127.44 1069.26,2132.09 2457.84,2133.48 220,2135 245,2135 25,2140 4455,2145 2799.8,2155.94 3936.65,2163.65 505,2165 700,2165 770,2165 3844.25,2164.48 2195,2170 1026.51,2174.83 1300,2175 1368.45,2175 1440,2175 1505,2175 1560,2175 1630,2175 2140,2175 2170,2175 2093.23,2178.83 2253.3,2179.75 2335,2180 2360,2180 2405,2180 2450,2180 2311.75,2180.54 2063.79,2183.73 4455,2185 638.41,2186.59 25,2190 455,2190 2750,2195 1300,2225 1368.45,2225 1440,2225 1505,2225 1560,2225 1630,2225 25,2230 450,2230 4455,2230 2445,2240 4431.72,2248.23 3124.72,2251.44 2750,2260 25,2265 1300,2275 1368.45,2275 1440,2275 1505,2275 1560,2275 1630,2275 4455,2275 2730,2280 1985,2285 2015,2285 3012,2291 2045,2295 4182.04,2295.44 25,2300 2445,2300 2230,2310 2290,2310 656.29,2310.34 4455,2320 1300,2325 1368.45,2325 1440,2325 1505,2325 1560,2325 1630,2325 2460,2325 2130,2330 2165,2330 2330,2330 2355,2330 2100,2335 2390,2340 2415,2340 2730,2345 25,2350 2460,2350 4455,2360 475,2365 670,2365 75,2370 2050,2370 25,2390 435,2390 2030,2390 75,2395 410,2395 836.56,2395.15 901.72,2395.69 2465,2400 4455,2400 455,2405 700,2410 25,2425 75,2430 320,2430 355,2430 385,2430 465,2445 900,2445 965,2445 4455,2445 510,2450 675,2450 65,2455 320,2455 25,2460 2270,2465 2330,2465 2725,2478.58 2235,2480 2655,2480 2375,2490 2425,2490 4455,2490 2165,2495 2200,2495 1885,2500 2135,2500 4289,2501 1910,2505 2400,2505 2455,2505 25,2510 1935,2530 4455,2535 25,2550 65,2565 1935,2565 798.39,2573.39 841.69,2573.39 885,2573.39 928.31,2573.39 971.61,2573.39 4455,2575 2651.58,2577.38 2718.53,2579.17 25,2585 1934.67,2592.27 1881.58,2612.97 1911.88,2612.67 4455,2615 798.39,2616.69 841.69,2616.69 885,2616.69 928.31,2616.69 971.61,2616.69 25,2620 375,2655 4455,2655 25,2660 798.39,2660 841.69,2660 885,2660 928.31,2660 971.61,2660 25,2700 4455,2700 798.39,2703.31 841.69,2703.31 885,2703.31 928.31,2703.31 971.61,2703.31 1520,2715 1750,2715 60,2720 25,2735 174.67,2743.9 65,2745 1535,2745 1580,2745 1625,2745 1675,2745 1715,2745 4455,2745 798.39,2746.61 841.69,2746.61 885,2746.61 928.31,2746.61 971.61,2746.61 320,2755 340,2755 177.51,2767.81 25,2770 4455,2785 25,2820 4455,2825 2005,2840 1945,2850 1875,2855 25,2860 70,2860 2000,2870 4455,2870 2380,2875 1830,2880 2075,2880 2110,2880 2275,2880 2305,2880 2345,2880 1745,2885 1785,2885 1640,2890 25,2895 2120,2905 2190,2905 2230,2905 1420,2910 1675,2915 4455,2915 25,2930 1420,2940 1450,2945 1675,2945 4455,2960 1695,2970 25,2975 1415,2980 4455,3000 1710,3010 25,3015 1415,3025 4455,3040 25,3050 1710,3050 1420,3070 25,3085 295,3085 335,3085 1685,3085 1425,3100 1475,3105 4455,3115 350,3125 25,3130 1680,3130 365,3155 4455,3160 25,3170 1460,3175 1635,3175 1495,3180 1515,3195 25,3205 4455,3205 1515,3220 470,3230 495,3230 525,3230 25,3240 4455,3245 1515,3250 75,3265 435,3265 4455,3285 25,3290 75,3290 435,3290 75,3315 435,3320 4455,3325 25,3330 75,3340 25,3365 4455,3370 25,3400 4455,3415 4455,3455 4455,3495 4455,3540 4455,3585 40,3620 65,3620 95,3620 4455,3630 40,3650 4455,3670 3160,3680 3380,3680 3530,3685 3745,3685 40,3690 4455,3710 40,3725 3380,3725 3160,3730 3530,3735 3745,3740 4440,3760 60,3765 4402.31,3786.39 90,3790 545,3795 2825,3800 2865,3800 2915,3800 2950,3800 2985,3800 3025,3800 3075,3800 3110,3800 3145,3800 3185,3800 3235,3800 3270,3800 3305,3800 3345,3800 3395,3800 3430,3800 3465,3800 3505,3800 3555,3800 3590,3800 3625,3800 3665,3800 3715,3800 3765,3800 3800,3800 3835,3800 3875,3800 3925,3800 3960,3800 3995,3800 4035,3800 4085,3800 4120,3800 4155,3800 4195,3800 4245,3800 4300,3800 4350,3800
  other v2: 2335.31,1735.31 2374.68,1735.31 2335.31,1774.68 2374.68,1774.68
  other v3: 251.65,2245 365,3273.35 365,3316.65
  other v4: 155,160 4310,160 155,3155 4310,3690
GPIO_VREF: J15.78 | length 49
  L01-TOP w6: v1(4209,2796) 4211.41,2798.41 4255.7,2798.41 J15.78@4256.64,2799.35
HDMI0_CEC: J7.13 J14.51 | length 1932.6
  L01-TOP w6: J14.51@3042.46,2594.62 3112.62,2594.62 v1(3114,2596)
  L01-TOP w7.27: J7.13@2518.74,3365 2518.74,3296.26 v1(2530,3285)
  L06-BOT w7.27: v1(2530,3285) 2530,3355 2660,3485 2855.74,3485 2860,3480.74 2860,3440 2950,3350 3060,3350 3325,3085 3325,2660 3255,2590 3200.7,2590 3194.7,2596 v1(3114,2596)
HDMI0_CLK_N: J14.90 L7.2 | length 581.1
  L01-TOP w5.38: L7.2@2503.9,3165 cw(c2500.57,3165) 2502.92,3162.65 2501.77,3161.49 ccw(c2506.91,3156.35) 2499.64,3156.35 2499.64,3153.88 2500,3153.51 2500,3090 2665,2925 2698.85,2891.15 2908.68,2891.15 2911.36,2893.83 J14.90@2921.2,2893.83
HDMI0_CLK_P: J14.88 L7.3 | length 598.3
  L01-TOP w5.38: L7.3@2485,3165 ccw(c2488.33,3165) 2485.97,3162.65 2487.13,3161.49 cw(c2481.99,3156.35) 2489.26,3156.35 2489.26,3149.58 2489.62,3149.22 2489.62,3085.7 2572.66,3002.66 2694.55,2880.77 2908.68,2880.77 2911.36,2878.09 J14.88@2921.2,2878.09
HDMI0_HP: J7.19 J14.53 | length 1422.1
  L01-TOP w6: J7.19@2636.85,3365 2636.85,3303.15 2645,3295 2675,3295 v1(2685,3285) ; J14.53@3042.46,2610.37 3043.4,2611.31 3085.69,2611.31 v1(3089,2614.62)
  L06-BOT w6: v1(2685,3285) 3015,3285 3265,3035 3265,2655 3224.62,2614.62 v1(3089,2614.62)
HDMI0_SCL: J7.15 J14.100 | length 723.1
  L01-TOP w6: J14.100@2921.2,2972.57 2945.57,2972.57 v1(2969,2996)
  L01-TOP w7.27: v1(2547.34,3247.15) 2558.11,3257.92 J7.15@2558.11,3365
  L06-BOT w7.27: v1(2547.34,3247.15) 2684.49,3110 2885,3110 2969,3026 v1(2969,2996)
HDMI0_SDA: J7.16 J14.99 | length 860.5
  L01-TOP w6: J14.99@3042.46,2972.57 3043.4,2973.51 3101.51,2973.51 v1(3104,2976)
  L01-TOP w7.27: J7.16@2577.8,3365 2577.8,3271.9 v1(2585.41,3264.28)
  L06-BOT w7.27: v1(2585.41,3264.28) 2644.69,3205 2970,3205 3104,3071 v1(3104,2976)
HDMI0_TX0_N: J14.84 L6.2 | length 670.2
  L01-TOP w5.38: L6.2@2430,3165.31 cw(c2426.67,3165.31) 2429.03,3162.96 2427.87,3161.81 ccw(c2433.01,3156.67) 2425.74,3156.67 2425.74,3145.74 ccw(c2427.53,3143.95) 2425,3143.95 2425,3100 2660,2865 2681.09,2843.91 2908.68,2843.91 2911.36,2846.59 J14.84@2921.2,2846.59
HDMI0_TX0_P: J14.82 L6.3 | length 687.4
  L01-TOP w5.38: L6.3@2411.1,3165.31 ccw(c2414.43,3165.31) 2412.08,3162.96 2413.23,3161.81 cw(c2408.09,3156.67) 2415.36,3156.67 2415.36,3151.09 cw(c2412.84,3151.09) 2414.62,3149.3 2414.62,3095.7 2607.66,2902.66 2676.8,2833.53 2908.68,2833.53 2911.36,2830.84 J14.82@2921.2,2830.84
HDMI0_TX1_N: J14.78 L5.2 | length 761.5
  L01-TOP w5.38: L5.2@2353.9,3165 cw(c2350.57,3165) 2352.92,3162.65 2351.77,3161.49 ccw(c2356.91,3156.35) 2349.64,3156.35 2349.64,3149.12 2350,3148.76 2350,3105 2658.34,2796.66 2908.68,2796.66 2911.36,2799.35 J14.78@2921.2,2799.35
HDMI0_TX1_P: J14.76 L5.3 | length 778.7
  L01-TOP w5.38: L5.3@2335,3165 ccw(c2338.33,3165) 2335.97,3162.65 2337.13,3161.49 cw(c2331.99,3156.35) 2339.26,3156.35 2339.26,3144.82 2339.62,3144.46 2339.62,3100.7 2562.66,2877.66 2632.66,2807.66 2654.04,2786.28 2908.68,2786.28 2911.36,2783.6 J14.76@2921.2,2783.6
HDMI0_TX2_N: J14.72 L4.2 | length 849.5
  L01-TOP w5.38: L4.2@2274.33,3165.32 cw(c2271,3165.32) 2273.36,3162.97 2272.2,3161.81 ccw(c2277.34,3156.67) 2270.07,3156.67 2270.07,3149.84 2270,3149.77 2270,3125 2630,2765 2645.58,2749.42 2908.68,2749.42 2911.36,2752.1 J14.72@2921.2,2752.1
HDMI0_TX2_P: J14.70 L4.3 | length 866.7
  L01-TOP w5.38: L4.3@2255.43,3165.32 ccw(c2258.76,3165.32) 2256.41,3162.97 2257.56,3161.81 cw(c2252.42,3156.67) 2259.69,3156.67 2259.69,3154.14 2259.62,3154.06 2259.62,3120.7 2557.66,2822.66 2641.28,2739.04 2908.68,2739.04 2911.36,2736.35 J14.70@2921.2,2736.35
I225_CLKREQ_N: R142.1 U18.3 | length 194.7
  L01-TOP w7.27: v1(655,2830) 685,2800 685,2760 714.13,2730.87 U18.3@750.16,2730.87
  L06-BOT w7.27: R142.1@651.37,2863.57 655,2859.95 v1(655,2830)
I225_DISABLE_N: R145.1 R147.2 U18.2 | length 219.2
  L01-TOP w7.27: v1(685.24,2838.77) 685.24,2824.76 700,2810 700,2765 718.39,2746.61 U18.2@750.16,2746.61
  L06-BOT w7.27: v1(685.24,2838.77) 685.24,2810.95 685.33,2810.95 698.17,2798.11 R147.2@733.68,2798.11
I225_JTAG_CLK: R149.2 U18.29 | length 113.2
  L01-TOP w7.27: U18.29@1019.84,2557.64 1036.73,2557.64 1046.91,2547.46 1055.3,2547.46 v1(1064.51,2556.67)
  L06-BOT w7.27: R149.2@1010.82,2571.5 1018.37,2563.96 1030.02,2563.96 1038.11,2555.86 1063.7,2555.86 v1(1064.51,2556.67)
I225_JTAG_RSTN: R148.2 U18.16 | length 171
  L01-TOP w7.27: v1(715,2470) 770,2470 798.39,2498.39 U18.16@798.39,2525.16
  L06-BOT w7.27: v1(715,2470) 744.29,2470 750.61,2463.68 750.69,2463.68 R148.2@758.24,2456.04 R148.2@758.24,2456.04
I225_LAN_PWR_GOOD: R144.1 U18.1 | length 139.5
  L01-TOP w7.27: v1(713.35,2830.86) 713.35,2771.65 722.64,2762.36 U18.1@750.16,2762.36
  L06-BOT w7.27: R144.1@712.2,2870 713.35,2868.85 v1(713.35,2830.86)
I225_PE_RX_N: R116.2 U18.27 | length 2477.6
  L01-TOP w5.38: U18.27@971.61,2525.16 971.61,2520.47 ccw(c976.2,2520.47) 972.96,2517.23 cw(c969.72,2513.99) 974.3,2513.99 974.3,2512.85 ccw(c1002.85,2512.85) 982.66,2492.66 ccw(c1002.07,2512.07) 1002.07,2484.62 1023.79,2484.62 ccw(c1023.79,2546.21) 1067.34,2502.66 1088.69,2524.01 ccw(c1057.09,2555.62) 1101.78,2555.62 cw(c1129.42,2555.62) 1109.88,2575.16 1179.9,2645.18 cw(c1250.61,2574.47) 1250.61,2674.47 1336.67,2674.47 ccw(c1336.67,2757.41) 1395.32,2698.76 1423.93,2727.37 ccw(c1396.31,2755) 1435.38,2755 1435.38,2760.84 cw(c1494.18,2760.84) 1452.6,2802.42 cw(c1482.96,2772.06) 1482.96,2815 1725.36,2815 cw(c1725.36,2715) 1796.07,2785.71 1849.83,2731.95 ccw(c1927.88,2810) 1927.88,2699.62 2557.63,2699.62 cw(c2557.63,2632.63) 2605,2680 2674.48,2610.52 cw(c2660.39,2596.44) 2680.31,2596.44 2680.31,2591.94 cw(c2671.24,2591.94) 2677.66,2585.53 2677.03,2584.91 ccw(c2681.94,2580) v1(2675,2580) ; v1(2700.31,2483.86) ccw(c2700.31,2480.37) 2697.84,2482.84 2695,2480 ccw(c2767.43,2480) 2716.21,2428.79 2731.87,2413.13 ccw(c2745,2426.25) 2745,2407.69 2755.5,2407.69 ccw(c2755.5,2416.02) 2761.39,2410.13 ccw(c2759.68,2411.84) 2762.1,2411.84 cw(c2764.52,2411.84) 2762.81,2413.56 2768.56,2419.3 cw(c2770.24,2417.62) R116.2@2770.24,2420
  L06-BOT w5.38: v1(2675,2580) ccw(c2681.94,2580) 2677.03,2575.09 cw(c2669.12,2567.18) 2680.31,2567.18 ccw(c2706.03,2567.18) 2687.84,2548.99 2703.17,2533.66 ccw(c2725,2555.49) 2725,2524.62 cw(c2725,2475.43) 2759.79,2510.21 cw(c2710.99,2461.42) 2780,2461.42 2780,2460 cw(c2742.65,2460) 2769.06,2433.59 2755.47,2420 cw(c2740.07,2435.41) 2740.07,2413.62 2715.41,2413.62 cw(c2715.41,2435.41) 2700,2420 cw(c2712.07,2432.07) 2695,2432.07 2695,2471.92 cw(c2704.07,2471.92) 2697.66,2478.33 2698.28,2478.96 ccw(c2693.37,2483.86) v1(2700.31,2483.86)
I225_PE_RX_P: R115.2 U18.28 | length 2527.5
  L01-TOP w5.38: U18.28@987.36,2525.16 987.36,2520.47 cw(c982.78,2520.47) 986.02,2517.23 ccw(c989.26,2513.99) 984.68,2513.99 984.68,2512.85 ccw(c1002.85,2512.85) 990,2500 ccw(c1002.07,2512.07) 1002.07,2495 1023.79,2495 ccw(c1023.79,2546.21) 1060,2510 1081.35,2531.35 ccw(c1057.09,2555.62) 1091.4,2555.62 cw(c1129.42,2555.62) 1102.54,2582.5 1172.56,2652.52 cw(c1250.61,2574.47) 1250.61,2684.85 1336.67,2684.85 ccw(c1336.67,2757.41) 1387.98,2706.1 1416.6,2734.71 ccw(c1396.31,2755) 1425,2755 1425,2760.84 cw(c1494.18,2760.84) 1445.26,2809.76 cw(c1482.96,2772.06) 1482.96,2825.38 1725.36,2825.38 cw(c1725.36,2715) 1803.41,2793.05 1857.17,2739.29 ccw(c1927.88,2810) 1927.88,2710 2557.63,2710 cw(c2557.63,2632.63) 2612.34,2687.34 2683.33,2616.34 cw(c2665.58,2598.59) 2690.69,2598.59 2690.69,2591.94 ccw(c2699.76,2591.94) 2693.34,2585.53 2693.97,2584.91 cw(c2689.06,2580) v1(2696,2580) ; v1(2679.31,2483.86) cw(c2679.31,2480.37) 2681.78,2482.84 2684.62,2480 ccw(c2767.43,2480) 2708.87,2421.45 2724.54,2405.79 ccw(c2745,2426.25) 2745,2397.31 2755.5,2397.31 cw(c2755.5,2388.98) 2761.39,2394.87 cw(c2759.68,2393.16) 2762.1,2393.16 ccw(c2764.52,2393.16) 2762.81,2391.44 2768.56,2385.7 ccw(c2770.24,2387.38) R115.2@2770.24,2385
  L06-BOT w5.38: v1(2679.31,2483.86) ccw(c2686.25,2483.86) 2681.34,2478.96 2681.97,2478.33 cw(c2675.56,2471.92) 2684.62,2471.92 2684.62,2432.07 ccw(c2712.07,2432.07) 2692.66,2412.66 ccw(c2715.41,2435.41) 2715.41,2403.24 2740.06,2403.24 ccw(c2740.06,2435.41) 2762.81,2412.66 2776.4,2426.25 ccw(c2742.65,2460) 2790.38,2460 2790.38,2468.79 ccw(c2728.79,2468.79) 2772.34,2512.34 2767.13,2517.55 ccw(c2725,2475.43) 2725,2535 cw(c2725,2555.49) 2710.51,2541 2695.18,2556.33 cw(c2706.03,2567.18) 2690.69,2567.18 cw(c2701.88,2567.18) 2693.97,2575.09 ccw(c2689.06,2580) v1(2696,2580)
I225_PE_TX_N: C184.2 U18.24 | length 2289.1
  L01-TOP w5.38: v1(921.74,2445) 921.74,2447.87 927.06,2453.19 927.06,2515.89 924.37,2518.58 U18.24@924.37,2525.16 ; v1(2730,2323) cw(c2730,2316.06) 2734.91,2320.97 2735.53,2320.34 ccw(c2741.94,2326.76) 2741.94,2317.69 2755.14,2317.69 ccw(c2755.14,2326.31) 2761.23,2320.21 ccw(c2759.73,2321.72) 2761.86,2321.72 cw(c2763.99,2321.72) 2762.48,2323.23 2768.29,2329.04 cw(c2770.61,2326.72) C184.2@2770.61,2330
  L06-BOT w5.38: v1(921.74,2445) cw(c928.68,2445) 923.78,2449.91 ccw(c915.86,2457.82) 927.06,2457.82 927.06,2459.67 cw(c937.43,2459.67) 930.09,2467.01 933.24,2470.15 cw(c970,2433.39) 970,2485.38 1093.98,2485.38 ccw(c1093.98,2585.38) 1164.69,2514.67 ccw(c1119.32,2560.04) 1183.48,2560.04 1183.48,2561.9 cw(c1257.43,2561.9) 1205.14,2614.19 1256.68,2665.73 cw(c1334.73,2587.68) 1334.73,2698.06 2327.94,2698.06 cw(c2327.94,2587.68) 2405.99,2665.73 2485.53,2586.2 cw(c2420.03,2520.7) 2512.66,2520.7 2512.66,2465.39 ccw(c2612.66,2465.39) 2541.95,2394.68 2589.65,2346.98 ccw(c2660.36,2417.69) 2660.36,2317.69 2718.06,2317.69 ccw(c2718.06,2326.76) 2724.47,2320.34 2725.09,2320.97 cw(c2730,2316.06) v1(2730,2323)
I225_PE_TX_P: C32.2 U18.25 | length 2272.1
  L01-TOP w5.38: U18.25@940.12,2525.16 940.12,2518.58 937.43,2515.89 937.43,2453.19 942.74,2447.87 v1(942.74,2445) ; v1(2730,2302) ccw(c2730,2308.94) 2734.91,2304.03 2735.53,2304.66 cw(c2741.94,2298.24) 2741.94,2307.31 2755.14,2307.31 cw(c2755.14,2298.69) 2761.23,2304.79 cw(c2759.73,2303.28) 2761.86,2303.28 ccw(c2763.99,2303.28) 2762.48,2301.77 2768.29,2295.96 ccw(c2770.61,2298.28) C32.2@2770.61,2295
  L06-BOT w5.38: v1(942.74,2445) ccw(c935.8,2445) 940.71,2449.91 cw(c948.63,2457.82) 937.43,2457.82 937.43,2459.67 940.58,2462.81 cw(c970,2433.39) 970,2475 1093.98,2475 ccw(c1093.98,2585.38) 1172.03,2507.33 1172.72,2508.02 ccw(c1121.68,2559.06) 1193.86,2559.06 1193.86,2561.9 cw(c1257.43,2561.9) 1212.48,2606.85 1264.02,2658.39 cw(c1334.73,2587.68) 1334.73,2687.68 2327.94,2687.68 cw(c2327.94,2587.68) 2398.65,2658.39 2472.99,2584.06 cw(c2402.28,2513.35) 2502.28,2513.35 2502.28,2465.39 ccw(c2612.66,2465.39) 2534.61,2387.35 2582.31,2339.64 ccw(c2660.36,2417.69) 2660.36,2307.31 2718.06,2307.31 cw(c2718.06,2298.24) 2724.47,2304.66 2725.09,2304.03 ccw(c2730,2308.94) v1(2730,2302)
I225_SCK: R112.1
I225_SDA: R113.1
I225_SDP0: J6.1 R121.1 | length 61.9
  L01-TOP w7.27: R121.1@95,1770.24 150.2,1770.24 J6.1@154.96,1775
I225_SDP1: J16.1 R133.1 | length 61.9
  L01-TOP w7.27: R133.1@95,1980.24 150.2,1980.24 J16.1@154.96,1985
I225_SDP2: R131.1
I225_SDP3: R132.1
I225_SPI_CLK: R125.2 R130.2 U20.16 | length 151.5
  L01-TOP w7.27: R130.2@309.81,1868.01 310.86,1869.06 R125.2@310.86,1900.67 310.86,1943.67 v1(290.51,1964.01) 290,1964.52 290,1980 296.08,1986.08 317.45,1986.08 U20.16@317.76,1986.38
I225_SPI_CS: R129.2 U20.12 | length 127.6
  L01-TOP w7.27: R129.2@340,2160.24 340,2092.36 330,2082.36 v1(330,2080) 341.38,2068.62 U20.12@341.38,2041.5
I225_SPI_DIN: R126.2 U20.9 | length 150.9
  L01-TOP w7.27: R126.2@375,2160.24 375,2130.2 410,2095.2 v1(410,2070) 395,2070 388.62,2063.62 U20.9@388.62,2041.5
I225_SPI_DOUT: R124.2 U20.3 | length 106.6
  L01-TOP w7.27: U20.3@372.87,1978.5 372.87,1948.97 408.46,1913.38 R124.2@435.24,1913.38
I225_ULP_WAKE_N: R141.1 U18.4 | length 111.9
  L01-TOP w7.27: v1(694.67,2724.67) 697.04,2724.67 706.59,2715.12 U18.4@750.16,2715.12
  L06-BOT w7.27: v1(694.67,2724.67) 694.67,2722.31 702.04,2714.95 702.04,2713.65 710.82,2704.87 726.14,2704.87 R141.1@733.69,2697.32
I225_WAKE_N: R143.1 U18.12 | length 205.2
  L01-TOP w7.27: v1(675.02,2486.5) 670,2491.53 670,2555 704.13,2589.13 U18.12@750.16,2589.13
  L06-BOT w7.27: R143.1@635,2487.2 635.7,2486.5 v1(675.02,2486.5)
I225_XTAL_IN: R138.2 U18.41 | length 127.2
  L01-TOP w7.27: U18.41@1019.84,2746.61 1045.74,2746.61 1074.12,2775 R138.2@1135.24,2775
I225_XTAL_OUT: R140.2 U18.40 | length 118.5
  L01-TOP w7.27: U18.40@1019.84,2730.87 1047.34,2730.87 1053.11,2736.63 1133.6,2736.63 R140.2@1135.24,2735
LED_ACT: J15.21 R26.1 | length 2668.1
  L01-TOP w6: R26.1@4114.59,186.07 4151.07,186.07 v1(4155,190) ; v1(4309,2361) 4310.56,2362.56 4324.16,2362.56 4325.72,2361 4342.28,2361 4344.88,2358.4 J15.21@4377.9,2358.4
  L03-SIG w4.97: v1(4071.69,1793.52) 4071.69,973.31 4175.98,869.02 4175.98,335.98 4030.59,190.59 4030.59,155.81 4033.5,152.9 4117.9,152.9 v1(4155,190)
  L04-SIG w4.97: v1(4071.69,1793.52) 4083.52,1793.52 4249.51,1959.51 4249.51,2301.51 v1(4309,2361)
LED_LINK_ACT#: R150.2 U18.30 | length 1595.3
  L01-TOP w7.27: U18.30@1019.84,2573.39 1019.96,2573.27 1044.23,2573.27 v1(1045,2572.5) ; v1(1118.66,3739.1) 1040,3660.44 1040,3355 1100,3295 1260,3295 1313.13,3241.87 1313.13,2933.11 1307.76,2927.74 v1(1307.76,2902.19)
  L04-SIG w4.97: v1(1045,2572.5) 1063.22,2572.5 1307.76,2817.04 v1(1307.76,2902.19)
  L06-BOT w7.27: v1(1118.66,3739.1) 1119.56,3740 R150.2@1160.24,3740
LED_PWR: J15.95 R27.1 | length 3164
  L01-TOP w6: R27.1@3985,171.73 3985,172.72 3993.81,181.53 3994.8,181.53 3998.64,185.37 v1(4057.19,185.37) ; 4318.79,2941.08 J15.95@4377.9,2941.08
  L03-SIG w6: v1(4057.19,185.37) 4100.37,185.37 4200.2,285.2 4200.2,954.8 4111.63,1043.37 4111.63,2002.32 4083.78,2030.17 4083.78,2788.78 4130,2835 4198,2835 v1(4309,2946)
LED_SPEED_1000#: R146.2 U18.32 | length 1526
  L01-TOP w7.27: v1(850,3635) 1020,3465 1020,3345 1090,3275 1250,3275 1290,3235 1290,2914.59 v1(1272.41,2897) ; U18.32@1019.84,2604.88 1019.96,2605 1044.23,2605 v1(1045,2605.77)
  L03-SIG w4.5: v1(1045,2605.77) 1046.02,2604.75 1077.5,2604.75 1103.4,2630.65 1103.4,2654.64 1121.07,2672.31
  L03-SIG w4.97: 1101.21,2652.45 1121.07,2672.31 1173.03,2724.27 1173.03,2797.55 v1(1272.41,2897)
  L06-BOT w7.27: R146.2@804.76,3635 v1(850,3635)
LED_SPEED_2500#: R151.2 U18.31 | length 1397.2
  L01-TOP w7.27: U18.31@1019.84,2589.13 v1(1057.82,2589.13) ; v1(1125,3540) 1070,3485 1070,3355 1115,3310 1270,3310 1330,3250 1330,2908.91 1333.3,2905.6 1333.3,2903.17 v1(1334.97,2901.5)
  L03-SIG w4.97: v1(1057.82,2589.13) 1100.54,2589.13 1120.78,2609.37 1120.78,2638.24 1334.97,2852.43 v1(1334.97,2901.5)
  L06-BOT w7.27: v1(1125,3540) R151.2@1170.24,3540
MDI_A_N: J17.10 U18.46 U23.4 U23.7 | length 375.6
  L01-TOP w5.38: U18.46@940.12,2794.84 940.12,2799.53 cw(c944.7,2799.53) 941.46,2802.77 ccw(c938.22,2806.01) 942.8,2806.01 942.8,2823.54 cw(c976.46,2823.54) 952.66,2847.34 952.99,2847.66 ccw(c937.65,2863) 959.34,2863 959.34,2869.75 ccw(c953.96,2869.75) 957.76,2873.55 956.19,2875.13 955.93,2875.13 cw(c958.95,2878.14) 954.68,2878.14 U23.4@954.68,2883.56 954.68,2889.87 cw(c956.82,2889.87) 955.31,2891.37 955.93,2892 956.19,2892 ccw(c948.58,2899.6) 959.34,2899.6 959.34,2902.63 ccw(c953.96,2902.63) 957.76,2906.43 956.19,2908 U23.7@955.93,2908 ; U23.7@954.68,2911.02 U23.7@954.68,2916.44 ; U23.7@954.72,2909.47 954.72,2921.95 cw(c958.85,2921.95) 955.93,2924.87 956.19,2924.87 957.76,2926.45 ccw(c953.96,2930.25) 959.34,2930.25 959.34,2934.47 cw(c974.9,2934.47) 963.9,2945.47 968.88,2950.46 cw(c991.92,2927.42) 991.92,2960 1072.93,2960 ccw(c1072.93,2977.07) 1085,2965 1087.61,2967.61 ccw(c1070.21,2985) 1094.81,2985 ccw(c1070.21,2985) 1087.61,3002.39 J17.10@1060,3030
MDI_A_P: J17.11 U18.45 U23.5 U23.6 | length 372
  L01-TOP w5.38: U18.45@955.87,2794.84 955.87,2799.53 ccw(c951.28,2799.53) 954.52,2802.77 cw(c957.76,2806.01) 953.18,2806.01 953.18,2823.54 cw(c976.46,2823.54) 960,2840 961.85,2841.85 ccw(c942.84,2860.85) 969.72,2860.85 969.72,2869.75 cw(c975.09,2869.75) 971.29,2873.55 972.87,2875.13 973.12,2875.13 ccw(c970.11,2878.14) 974.37,2878.14 U23.5@974.37,2883.56 974.37,2889.87 ccw(c972.24,2889.87) 973.75,2891.37 973.12,2892 972.87,2892 cw(c980.47,2899.6) 969.72,2899.6 969.72,2902.63 cw(c975.09,2902.63) 971.29,2906.43 972.87,2908 973.12,2908 ccw(c970.11,2911.02) 974.37,2911.02 U23.6@974.37,2916.44 974.37,2921.86 ccw(c970.11,2921.86) 973.12,2924.87 972.87,2924.87 971.29,2926.45 cw(c975.09,2930.25) 969.72,2930.25 969.72,2932.32 cw(c980.09,2932.32) 972.76,2939.66 976.22,2943.12 cw(c991.92,2927.42) 991.92,2949.62 1072.93,2949.62 ccw(c1072.93,2977.07) 1092.34,2957.66 1094.94,2960.27 ccw(c1070.21,2985) 1105.19,2985 cw(c1129.79,2985) 1112.39,3002.39 J17.11@1140,3030
MDI_B_N: J17.5 U18.49 U23.1 U23.10 | length 893.3
  L01-TOP w5.38: U18.49@892.87,2794.84 892.87,2799.53 cw(c897.46,2799.53) 894.22,2802.77 ccw(c890.98,2806.01) 895.56,2806.01 895.56,2811.79 ccw(c893.21,2811.79) 894.87,2813.45 894.87,2837.45 cw(c905.25,2837.45) 897.91,2844.79 ccw(c892.18,2850.52) 900.28,2850.52 900.28,2868.5 ccw(c891.89,2868.5) 897.83,2874.44 897.13,2875.13 896.88,2875.13 896.25,2875.75 cw(c897.76,2877.26) 895.63,2877.26 U23.1@895.63,2883.56 895.63,2889.87 cw(c897.76,2889.87) 896.25,2891.37 896.88,2892 897.13,2892 ccw(c889.53,2899.6) 900.28,2899.6 900.28,2902.63 ccw(c894.91,2902.63) 898.71,2906.43 897.13,2908 U23.10@896.88,2908 ; U23.10@895.63,2911.02 U23.10@895.63,2916.44 ; U23.10@895.67,2909.47 895.67,2921.95 cw(c899.8,2921.95) 896.88,2924.87 897.13,2924.87 898.71,2926.45 ccw(c894.91,2930.25) 900.28,2930.25 900.28,2932.54 cw(c928.18,2932.54) 908.45,2952.27 916.09,2959.91 cw(c946.7,2929.31) 946.7,2972.58 ccw(c946.7,2990.59) 959.43,2977.86 991.71,3010.14 ccw(c959.64,3042.22) 1005,3042.22 1005,3048.84 cw(c1031.16,3048.84) 1012.66,3067.34 cw(c1067.37,3012.63) 1067.37,3090 1215,3090 ccw(c1166.72,3138.28) 1235,3138.28 1235,3150 ccw(c1198.79,3150) 1224.39,3175.61 1200,3200 ccw(c1163.79,3163.79) 1163.79,3215 1109.14,3215 ccw(c1109.14,3180.86) 1085,3205 1072.39,3192.39 ccw(c1089.79,3175) 1065.19,3175 ccw(c1089.79,3175) 1072.39,3157.61 J17.5@1100,3130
